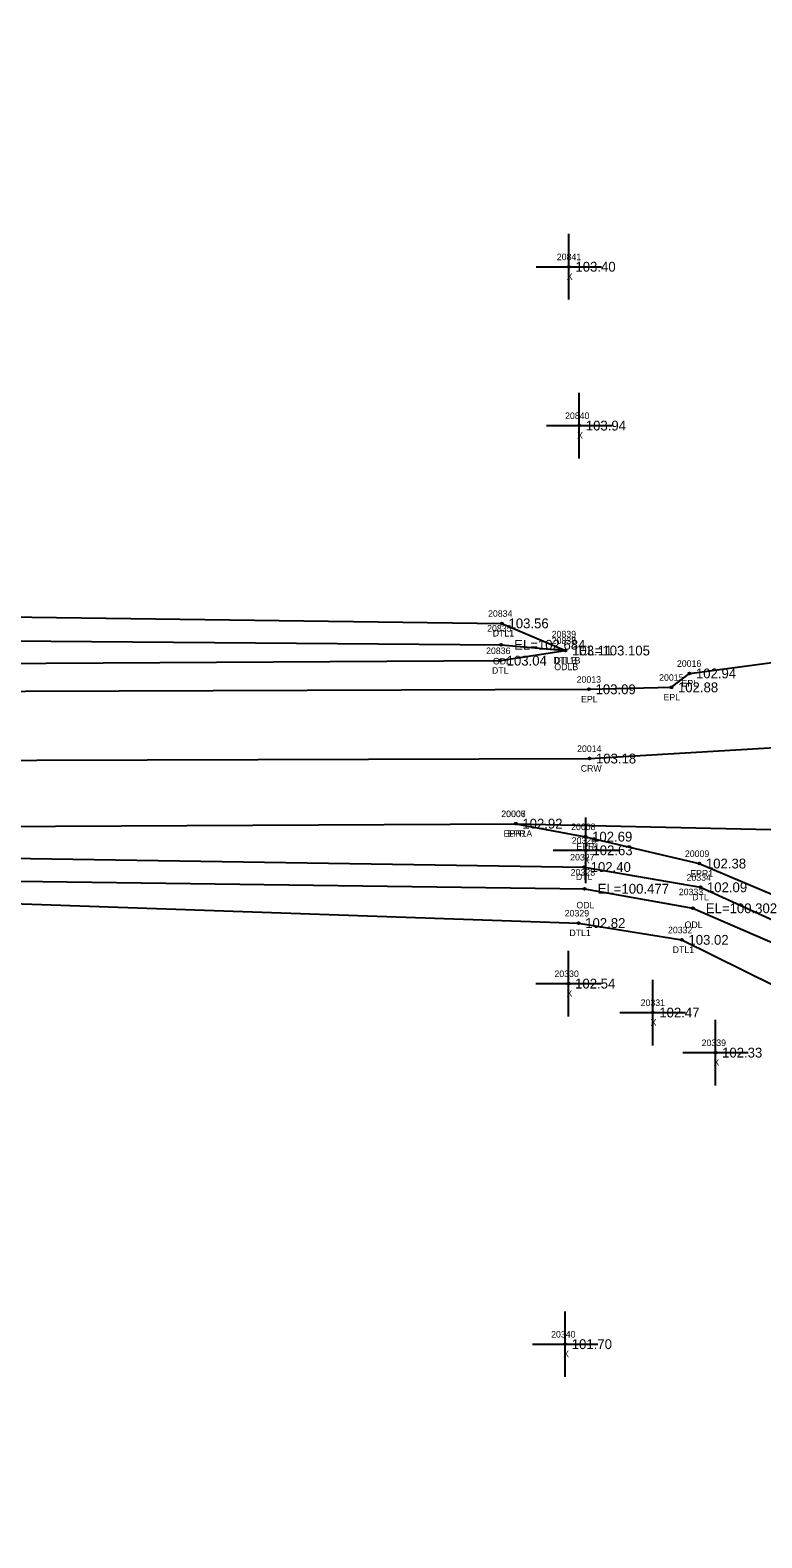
# Model space of a CAD drawing. Extents: x 2530197 to 2532051, y 935230 to 936631.
# Drawn here: x 2530328.9 to 2530440.5, y 935471.7 to 935701.6 of the extents above; entities that cross this region are included whole.
import ezdxf

# ---------------------------------------------------------------- set-up
doc = ezdxf.new("R2010")
doc.units = 0
for name, color, linetype in [('RD_DTM_BkLn1', 7, 'Continuous'), ('RD_EX_H2O', 7, 'Continuous'), ('RD_EX_H2O_txCode', 7, 'Continuous'), ('RD_EX_Misc', 7, 'Continuous'), ('RD_EX_Misc_txCode', 7, 'Continuous'), ('RD_EX_Road', 7, 'Continuous'), ('RD_EX_Road_txCode', 7, 'Continuous'), ('RD_EX_TX_H2O_ELEV', 7, 'Continuous'), ('RD_EX_TX_Misc_ELEV', 7, 'Continuous'), ('RD_EX_TX_Road_ELEV', 7, 'Continuous'), ('RD_HC_Survey_ELEV', 7, 'Continuous'), ('RD_HC_Survey_txCode', 7, 'Continuous'), ('RD_SMD_Locator', 7, 'Continuous')]:
    doc.layers.add(name, color=color, linetype=linetype)

msp = doc.modelspace()

# ---------------------------------------------------------------- linework, layer by layer
at = {"layer": 'RD_DTM_BkLn1'}
msp.add_lwpolyline([(2530212.5, 935590.24), (2530312.97, 935590.25), (2530414.21, 935590.57), (2530470.01, 935593.88), (2530526.51, 935611.77), (2530574.01, 935635.84), (2530615.35, 935659.73), (2530701.7, 935710.7), (2530789.3, 935762.35), (2530874.46, 935813.14), (2530961.78, 935865.4), (2531046.63, 935916.04), (2531084.76, 935938.51)], dxfattribs=at)
at = {"layer": 'RD_EX_H2O'}
for points in [[(2530213.15, 935611.64), (2530313.99, 935612.32), (2530400.87, 935611.18), (2530410.57, 935607.04)], [(2530213.01, 935607.47), (2530313.25, 935608.62), (2530400.73, 935607.92), (2530410.57, 935607.04)], [(2530213.2, 935602.99), (2530313.99, 935605.02), (2530400.59, 935605.5), (2530410.57, 935607.04)], [(2530212.43, 935575.3), (2530312.61, 935575.57), (2530413.4, 935574.03), (2530431.14, 935570.94), (2530447.74, 935563.43), (2530459.72, 935547.88), (2530491.74, 935452.52), (2530522.77, 935357.57), (2530554.82, 935263)], [(2530212.28, 935572.05), (2530311.96, 935572.07), (2530413.48, 935570.72), (2530429.97, 935567.74), (2530445.97, 935560.86), (2530457.18, 935547.13), (2530489.52, 935451.8), (2530520.38, 935357.21), (2530552.97, 935262.56)], [(2530212.78, 935569.06), (2530311.54, 935568.98), (2530412.57, 935565.49), (2530428.32, 935562.93), (2530442.59, 935555.84), (2530453.4, 935544.85), (2530485.1, 935450.23), (2530516.56, 935356.42), (2530549.63, 935261.88)]]:
    msp.add_lwpolyline(points, dxfattribs=at)
at = {"layer": 'RD_EX_Misc'}
for p, q in [((2530411.08, 935660.56), (2530411.08, 935670.56)), ((2530406.08, 935665.56), (2530416.08, 935665.56)), ((2530412.66, 935636.34), (2530412.66, 935646.34)), ((2530407.66, 935641.34), (2530417.66, 935641.34)), ((2530413.67, 935571.58), (2530413.67, 935581.58)), ((2530408.67, 935576.58), (2530418.67, 935576.58)), ((2530411.03, 935551.25), (2530411.03, 935561.25)), ((2530423.87, 935546.84), (2530423.87, 935556.84)), ((2530406.03, 935556.25), (2530416.03, 935556.25)), ((2530418.87, 935551.84), (2530428.87, 935551.84)), ((2530433.45, 935540.73), (2530433.45, 935550.73)), ((2530428.45, 935545.73), (2530438.45, 935545.73)), ((2530410.52, 935496.28), (2530410.52, 935506.28)), ((2530405.52, 935501.28), (2530415.52, 935501.28))]:
    msp.add_line(p, q, dxfattribs=at)
at = {"layer": 'RD_EX_Road'}
for points in [[(2530213.13, 935600.16), (2530313.8, 935600.81), (2530414.15, 935601.13), (2530426.72, 935601.43), (2530429.46, 935603.55), (2530467.67, 935608.62), (2530486.46, 935612.38), (2530518.02, 935622.55), (2530522.16, 935623.68), (2530567.91, 935646.01), (2530609.3, 935670.15), (2530695.46, 935720.02), (2530775.85, 935769.27), (2530868.29, 935824.03), (2530924.84, 935856.95), (2530956.21, 935875.82), (2531040.72, 935926.38), (2531079.45, 935947.76)], [(2530212.44, 935579.72), (2530312.61, 935580.14), (2530402.98, 935580.64), (2530451.06, 935579.53), (2530466.91, 935580.35), (2530487.45, 935583.29), (2530533.43, 935598.45), (2530580.28, 935625.08), (2530621.69, 935649.23), (2530704.62, 935698.35), (2530718.67, 935706.38), (2530795.45, 935752.36), (2530871.33, 935796.67), (2530882.4, 935803.04), (2530947.17, 935842.26), (2530966, 935852.42), (2530992.72, 935868), (2531009.49, 935879.01), (2531052.39, 935904.85), (2531090.88, 935928.23)], [(2530402.98, 935580.64), (2530413.62, 935578.66), (2530430.98, 935574.56), (2530444.41, 935568.86), (2530451.97, 935562.31), (2530461.09, 935548.32), (2530494.98, 935453.81), (2530526.54, 935359.14), (2530558.58, 935263.43)]]:
    msp.add_lwpolyline(points, dxfattribs=at)
at = {"layer": 'RD_SMD_Locator'}
for centre in [(2530411.08, 935665.56), (2530412.66, 935641.34), (2530400.87, 935611.18), (2530400.73, 935607.92), (2530410.57, 935607.04), (2530410.57, 935607.04), (2530410.57, 935607.04), (2530400.59, 935605.5), (2530429.46, 935603.55), (2530414.15, 935601.13), (2530426.72, 935601.43), (2530414.21, 935590.57), (2530402.98, 935580.64), (2530402.98, 935580.64), (2530413.62, 935578.66), (2530413.67, 935576.58), (2530413.4, 935574.03), (2530430.98, 935574.56), (2530413.48, 935570.72), (2530431.14, 935570.94), (2530429.97, 935567.74), (2530412.57, 935565.49), (2530428.32, 935562.93), (2530411.03, 935556.25), (2530423.87, 935551.84), (2530433.45, 935545.73), (2530410.52, 935501.28)]:
    msp.add_circle(centre, 0.15, dxfattribs=at)

# ---------------------------------------------------------------- texts
at = {"layer": 'RD_EX_H2O_txCode'}
for s, p in [('20834', (2530398.75, 935612.18)), ('20835', (2530398.61, 935609.92)), ('DTL1', (2530399.46, 935609.18)), ('20839', (2530408.46, 935609.04)), ('20836', (2530398.45, 935606.5)), ('20837', (2530408.46, 935608.04)), ('20838', (2530408.46, 935608.04)), ('ODL', (2530399.49, 935604.92)), ('DTL1B', (2530408.69, 935605.04)), ('ODLB', (2530408.86, 935604.04)), ('DTLB', (2530408.86, 935605.04)), ('DTL', (2530399.35, 935603.5)), ('20327', (2530411.28, 935575.03)), ('20328', (2530411.36, 935572.72)), ('DTL', (2530412.15, 935572.03)), ('20334', (2530429.03, 935571.94)), ('20333', (2530427.85, 935569.74)), ('ODL', (2530412.23, 935567.72)), ('DTL', (2530429.9, 935568.94)), ('20329', (2530410.45, 935566.49)), ('DTL1', (2530411.16, 935563.49)), ('20332', (2530426.2, 935563.93)), ('ODL', (2530428.73, 935564.74)), ('DTL1', (2530426.91, 935560.93))]:
    msp.add_text(s, height=1, dxfattribs=at).set_placement(p)
at = {"layer": 'RD_EX_Misc_txCode'}
for s, p in [('20841', (2530409.24, 935666.56)), ('X', (2530410.76, 935663.56)), ('20840', (2530410.5, 935642.34)), ('X', (2530412.34, 935639.34)), ('20326', (2530411.52, 935577.58)), ('X', (2530413.35, 935574.58)), ('20330', (2530408.88, 935557.25)), ('X', (2530410.72, 935554.25)), ('20331', (2530422.03, 935552.84)), ('X', (2530423.55, 935549.84)), ('20339', (2530431.33, 935546.73)), ('X', (2530433.14, 935543.73)), ('20340', (2530408.37, 935502.28)), ('X', (2530410.21, 935499.28))]:
    msp.add_text(s, height=1, dxfattribs=at).set_placement(p)
at = {"layer": 'RD_EX_Road_txCode'}
for s, p in [('20016', (2530427.56, 935604.55)), ('20013', (2530412.27, 935602.13)), ('20015', (2530424.85, 935602.43)), ('EPL', (2530425.52, 935599.43)), ('EPL', (2530428.26, 935601.55)), ('EPL', (2530412.94, 935599.13)), ('20006', (2530400.76, 935581.64)), ('20007', (2530400.78, 935581.64)), ('EPR1A', (2530401.1, 935578.64)), ('EPR', (2530401.75, 935578.64)), ('20008', (2530411.42, 935579.66)), ('EPR1', (2530412.23, 935576.66)), ('20009', (2530428.78, 935575.56)), ('EPR1', (2530429.59, 935572.56))]:
    msp.add_text(s, height=1, dxfattribs=at).set_placement(p)
at = {"layer": 'RD_EX_TX_H2O_ELEV'}
for s, p in [('103.56', (2530401.87, 935610.43)), ('EL=102.684', (2530402.73, 935607.17)), ('103.11', (2530411.57, 935606.29)), ('103.11', (2530411.57, 935606.29)), ('EL=103.105', (2530412.57, 935606.29)), ('103.04', (2530401.59, 935604.75)), ('102.40', (2530414.4, 935573.28)), ('EL=100.477', (2530415.48, 935569.97)), ('102.09', (2530432.14, 935570.19)), ('EL=100.302', (2530431.97, 935566.99)), ('102.82', (2530413.57, 935564.74)), ('103.02', (2530429.32, 935562.18))]:
    msp.add_text(s, height=1.5, dxfattribs=at).set_placement(p)
at = {"layer": 'RD_EX_TX_Misc_ELEV'}
for s, p in [('103.40', (2530412.08, 935664.81)), ('103.94', (2530413.66, 935640.59)), ('102.63', (2530414.67, 935575.83)), ('102.54', (2530412.03, 935555.5)), ('102.47', (2530424.87, 935551.09)), ('102.33', (2530434.45, 935544.98)), ('101.70', (2530411.52, 935500.53))]:
    msp.add_text(s, height=1.5, dxfattribs=at).set_placement(p)
at = {"layer": 'RD_EX_TX_Road_ELEV'}
for s, p in [('102.94', (2530430.46, 935602.8)), ('103.09', (2530415.15, 935600.38)), ('102.88', (2530427.72, 935600.68)), ('102.92', (2530403.98, 935579.89)), ('102.92', (2530403.98, 935579.89)), ('102.69', (2530414.62, 935577.91)), ('102.38', (2530431.98, 935573.81))]:
    msp.add_text(s, height=1.5, dxfattribs=at).set_placement(p)
at = {"layer": 'RD_HC_Survey_ELEV'}
msp.add_text('103.18', height=1.5, dxfattribs=at).set_placement((2530415.21, 935589.82))
at = {"layer": 'RD_HC_Survey_txCode'}
for s, p in [('20014', (2530412.33, 935591.57)), ('CRW', (2530412.89, 935588.57))]:
    msp.add_text(s, height=1, dxfattribs=at).set_placement(p)

doc.saveas('drawing.dxf')
